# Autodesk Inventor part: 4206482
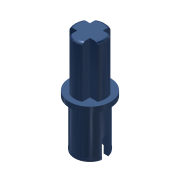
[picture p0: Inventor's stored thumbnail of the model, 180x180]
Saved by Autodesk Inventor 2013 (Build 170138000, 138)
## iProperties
Created: 2013-03
Part Number: 4206482
Material: Generic
Document SubType Name: Modeling
Designer: perblt
Density: 1 g/cm^3
Author: perblt
Translation Standard: STEP AP203
FileName: 4206482
PreProcessor: PRO/ENGINEER BY PARAMETRIC TECHNOLOGY CORPORATION, 2010370
PostProcessor: Build: 138, Release: 2013 RTM - Date: Thu 03/01/2012
Sent Units: millimeter
Uncertainty: 0.001838370095962
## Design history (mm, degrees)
node "42064821"
node "4206482"
node "Base1"
